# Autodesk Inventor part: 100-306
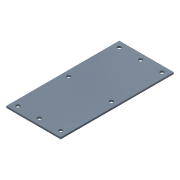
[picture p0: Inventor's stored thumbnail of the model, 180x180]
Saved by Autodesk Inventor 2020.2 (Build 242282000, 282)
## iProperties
Created: 2011-01
Part Number: 100-306
Document SubType Name: Modeling
Designer: F.Stasiak
Density: 1 g/cm^3
Material: Ogólny
Appearance: Stalowoniebieska
Company: Fabian Stasiak CAD Consulting
Manager: www.cadconsulting.pl
Author: F.Stasiak
Subject: Zbiór ćwiczeń. Autodesk Inventor 2020. Kurs podstawowy
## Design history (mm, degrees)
sketch "Szkic1"
  geometry: L1 (-93, 193)-(-93, -193) reference; L2 (-93, -193)-(93, -193) reference; L3 (93, -193)-(93, 193) reference; L4 (93, 193)-(-93, 193) reference; L5 (-50, -150)-(-50, 150) reference; L6 (-50, 150)-(50, 150) reference; L7 (50, 150)-(50, -150) reference; L8 (50, -150)-(-50, -150) reference; C1 r 6.5 at (-73, 173) reference; C2 r 6.5 at (0, 173) reference; C3 r 6.5 at (-73, 0) reference; C4 r 6.5 at (-73, -173) reference; C5 r 6.5 at (0, -173) reference; C6 r 6.5 at (73, -173) reference; C7 r 6.5 at (73, 0) reference; C8 r 6.5 at (73, 173) reference; 1 further point
extrude "Wyciągnięcie proste1" new body sketch "Szkic1" distance "d0" = 6; taper "d1" = 0 deg
node "Bryła1"
node "Odniesienie1"
